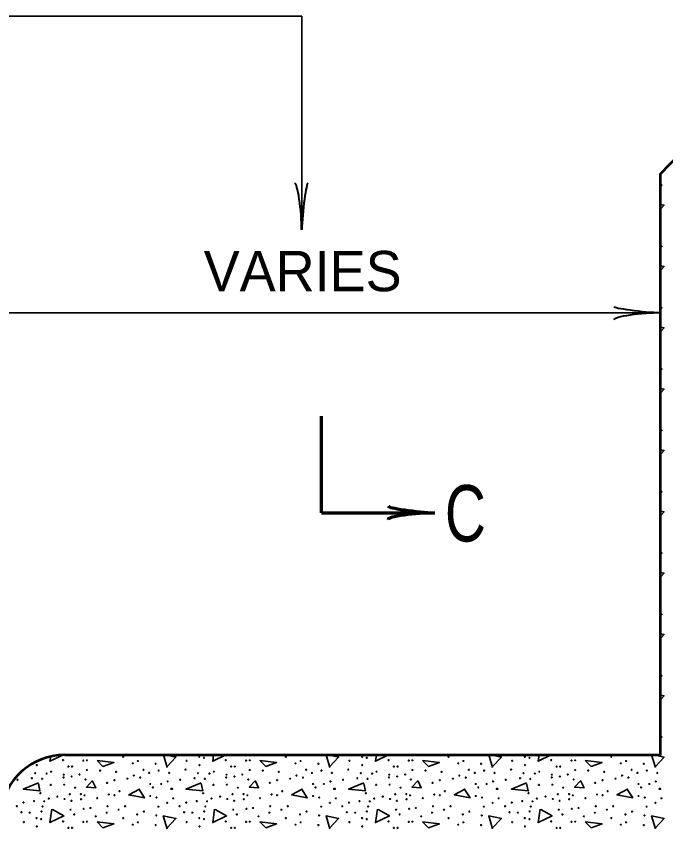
# Model space of a CAD drawing. Extents: x -105 to 751, y -65 to 479.
# Drawn here: x 57.8 to 106.1, y 28.3 to 88.7 of the extents above; entities that cross this region are included whole.
import ezdxf

# ---------------------------------------------------------------- set-up
doc = ezdxf.new("R2010")
doc.units = 0
doc.header["$LTSCALE"] = 1.2
doc.layers.add('1', color=7, linetype='Continuous', lineweight=35)

msp = doc.modelspace()

# ---------------------------------------------------------------- linework, layer by layer
at = {"layer": '1', "lineweight": 70}
for q in [(80.525, 58.96), (88.925, 51.76)]:
    msp.add_line((80.525, 51.76), q, dxfattribs=at)
at = {"layer": '1'}
for p, q in [((69.062, 32.832), (68.784, 33.76)), ((81.158, 32.832), (80.88, 33.76)), ((93.254, 32.832), (92.976, 33.76)), ((105.35, 32.832), (105.072, 33.76))]:
    msp.add_line(p, q, dxfattribs=at)
for points in [[(50.512, 88.687), (79.059, 88.687), (79.059, 72.823)], [(105.725, 74.696), (105.998, 74.64), (105.725, 74.347)], [(105.725, 70.136), (105.998, 70.08), (105.725, 69.787)], [(-1.897, 66.639), (54.365, 66.639), (105.725, 66.639)], [(105.725, 65.576), (105.998, 65.52), (105.725, 65.227)], [(105.725, 61.016), (105.998, 60.96), (105.725, 60.667)], [(105.725, 56.456), (105.998, 56.4), (105.725, 56.107)], [(105.725, 51.896), (105.998, 51.84), (105.725, 51.547)], [(105.725, 47.336), (105.998, 47.28), (105.725, 46.987)], [(105.725, 42.776), (105.998, 42.72), (105.725, 42.427)], [(105.725, 38.216), (105.998, 38.16), (105.725, 37.867)], [(61.299, 33.751), (60.35, 33.288), (60.387, 33.549)], [(68.929, 33.76), (69.71, 33.6), (69.038, 32.88)], [(73.413, 33.76), (72.446, 33.288), (72.513, 33.76)], [(81.025, 33.76), (81.806, 33.6), (81.134, 32.88)], [(85.509, 33.76), (84.542, 33.288), (84.609, 33.76)], [(93.121, 33.76), (93.902, 33.6), (93.23, 32.88)], [(97.605, 33.76), (96.638, 33.288), (96.705, 33.76)], [(105.217, 33.76), (105.998, 33.6), (105.326, 32.88)], [(59.486, 31.68), (58.358, 31.224), (59.606, 31.08), (59.486, 31.632)], [(63.518, 31.848), (63.062, 31.368), (63.758, 31.32), (63.518, 31.8)], [(71.582, 31.68), (70.454, 31.224), (71.702, 31.08), (71.582, 31.632)], [(75.614, 31.848), (75.158, 31.368), (75.854, 31.32), (75.614, 31.8)], [(83.678, 31.68), (82.55, 31.224), (83.798, 31.08), (83.678, 31.632)], [(87.71, 31.848), (87.254, 31.368), (87.95, 31.32), (87.71, 31.8)], [(95.774, 31.68), (94.646, 31.224), (95.894, 31.08), (95.774, 31.632)], [(99.806, 31.848), (99.35, 31.368), (100.046, 31.32), (99.806, 31.8)], [(66.998, 31.224), (66.206, 30.792), (67.382, 30.576), (66.95, 31.248)], [(79.094, 31.224), (78.302, 30.792), (79.478, 30.576), (79.046, 31.248)], [(91.19, 31.224), (90.398, 30.792), (91.574, 30.576), (91.142, 31.248)], [(103.286, 31.224), (102.494, 30.792), (103.67, 30.576), (103.238, 31.248)], [(60.542, 29.712), (61.382, 29.232), (60.35, 28.728), (60.494, 29.736)], [(72.638, 29.712), (73.478, 29.232), (72.446, 28.728), (72.59, 29.736)], [(84.734, 29.712), (85.574, 29.232), (84.542, 28.728), (84.686, 29.736)], [(96.83, 29.712), (97.67, 29.232), (96.638, 28.728), (96.782, 29.736)], [(69.062, 28.272), (68.774, 29.232), (69.71, 29.04), (69.038, 28.32)], [(81.158, 28.272), (80.87, 29.232), (81.806, 29.04), (81.134, 28.32)], [(93.254, 28.272), (92.966, 29.232), (93.902, 29.04), (93.23, 28.32)], [(105.35, 28.272), (105.062, 29.232), (105.998, 29.04), (105.326, 28.32)]]:
    msp.add_lwpolyline(points, dxfattribs=at)
at = {"layer": '1', "lineweight": 53}
msp.add_lwpolyline([(61.447, 33.76), (105.725, 33.76), (105.725, 76.96), (109.893, 81.276)], dxfattribs=at)
at = {"layer": '1'}
for points in [[(63.854, 33.336), (65.102, 33.192), (64.286, 32.904)], [(75.95, 33.336), (77.198, 33.192), (76.382, 32.904)], [(88.046, 33.336), (89.294, 33.192), (88.478, 32.904)], [(100.142, 33.336), (101.39, 33.192), (100.574, 32.904)], [(63.854, 28.776), (65.102, 28.632), (64.286, 28.344)], [(75.95, 28.776), (77.198, 28.632), (76.382, 28.344)], [(88.046, 28.776), (89.294, 28.632), (88.478, 28.344)], [(100.142, 28.776), (101.39, 28.632), (100.574, 28.344)]]:
    msp.add_lwpolyline(points, close=True, dxfattribs=at)
for centre in [(105.797, 76.132), (105.797, 71.572), (105.797, 67.012), (105.797, 62.452), (105.797, 57.892), (105.797, 53.332), (105.797, 48.772), (105.797, 44.212), (105.797, 39.652), (105.797, 35.092), (61.325, 33.374), (62.829, 33.34), (63.1, 33.358), (65.788, 33.629), (66.885, 33.311), (70.511, 33.326), (71.449, 33.629), (71.799, 33.549), (73.421, 33.374), (74.925, 33.34), (75.196, 33.358), (77.884, 33.629), (78.981, 33.311), (82.607, 33.326), (83.545, 33.629), (83.895, 33.549), (85.517, 33.374), (87.021, 33.34), (87.292, 33.358), (89.98, 33.629), (91.077, 33.311), (94.703, 33.326), (95.641, 33.629), (95.991, 33.549), (97.613, 33.374), (99.117, 33.34), (99.388, 33.358), (102.076, 33.629), (103.173, 33.311), (59.369, 33.008), (61.723, 32.897), (61.993, 32.897), (63.1, 32.642), (64.07, 32.595), (66.503, 33.136), (67.299, 32.658), (68.205, 33.104), (68.428, 32.595), (70.432, 32.674), (71.465, 33.008), (73.819, 32.897), (74.089, 32.897), (75.196, 32.642), (76.166, 32.595), (78.599, 33.136), (79.395, 32.658), (80.301, 33.104), (80.524, 32.595), (82.528, 32.674), (83.561, 33.008), (85.915, 32.897), (86.185, 32.897), (87.292, 32.642), (88.262, 32.595), (90.695, 33.136), (91.491, 32.658), (92.397, 33.104), (92.62, 32.595), (94.624, 32.674), (95.657, 33.008), (98.011, 32.897), (98.281, 32.897), (99.388, 32.642), (100.358, 32.595), (102.791, 33.136), (103.587, 32.658), (104.493, 33.104), (104.716, 32.595), (59.004, 32.028), (59.258, 32.404), (60.101, 32.372), (60.435, 32.515), (61.357, 32.091), (61.373, 32.292), (61.962, 32.155), (62.55, 32.308), (65.263, 32.499), (66.106, 31.996), (66.583, 32.229), (67.06, 32.075), (67.728, 32.42), (69.207, 32.42), (71.1, 32.028), (71.354, 32.404), (72.197, 32.372), (72.531, 32.515), (73.453, 32.091), (73.469, 32.292), (74.058, 32.155), (74.646, 32.308), (77.359, 32.499), (78.202, 31.996), (78.679, 32.229), (79.156, 32.075), (79.824, 32.42), (81.303, 32.42), (83.196, 32.028), (83.45, 32.404), (84.293, 32.372), (84.627, 32.515), (85.549, 32.091), (85.565, 32.292), (86.154, 32.155), (86.742, 32.308), (89.455, 32.499), (90.298, 31.996), (90.775, 32.229), (91.252, 32.075), (91.92, 32.42), (93.399, 32.42), (95.292, 32.028), (95.546, 32.404), (96.389, 32.372), (96.723, 32.515), (97.645, 32.091), (97.661, 32.292), (98.25, 32.155), (98.838, 32.308), (101.551, 32.499), (102.394, 31.996), (102.871, 32.229), (103.348, 32.075), (104.016, 32.42), (105.495, 32.42), (57.938, 31.916), (59.767, 31.98), (60.403, 31.535), (61.405, 31.55), (62.989, 31.932), (64.595, 31.678), (65.136, 31.884), (67.807, 31.598), (68.619, 31.598), (69.096, 31.789), (70.034, 31.916), (71.863, 31.98), (72.499, 31.535), (73.501, 31.55), (75.085, 31.932), (76.691, 31.678), (77.232, 31.884), (79.903, 31.598), (80.715, 31.598), (81.192, 31.789), (82.13, 31.916), (83.959, 31.98), (84.595, 31.535), (85.597, 31.55), (87.181, 31.932), (88.787, 31.678), (89.328, 31.884), (91.999, 31.598), (92.811, 31.598), (93.288, 31.789), (94.226, 31.916), (96.055, 31.98), (96.691, 31.535), (97.693, 31.55), (99.277, 31.932), (100.883, 31.678), (101.424, 31.884), (104.095, 31.598), (104.907, 31.598), (105.384, 31.789), (59.64, 30.914), (61.818, 30.835), (62.216, 31.328), (62.646, 30.85), (64.722, 30.819), (65.517, 31.057), (67.998, 31.344), (69.366, 31.232), (69.43, 31.232), (71.736, 30.914), (73.914, 30.835), (74.312, 31.328), (74.742, 30.85), (76.818, 30.819), (77.613, 31.057), (80.094, 31.344), (81.462, 31.232), (81.526, 31.232), (83.832, 30.914), (86.01, 30.835), (86.408, 31.328), (86.838, 30.85), (88.914, 30.819), (89.709, 31.057), (92.19, 31.344), (93.558, 31.232), (93.622, 31.232), (95.928, 30.914), (98.106, 30.835), (98.504, 31.328), (98.934, 30.85), (101.01, 30.819), (101.805, 31.057), (104.286, 31.344), (105.654, 31.232), (105.718, 31.232), (58.383, 30.214), (59.163, 30.326), (59.926, 30.31), (60.26, 30.516), (60.896, 30.66), (61.437, 30.485), (61.946, 30.357), (62.661, 30.469), (62.925, 30.755), (63.863, 30.548), (65.136, 30.771), (67.807, 30.707), (68.269, 30.596), (69.064, 30.198), (69.509, 30.532), (70.479, 30.214), (71.259, 30.326), (72.022, 30.31), (72.356, 30.516), (72.992, 30.66), (73.533, 30.485), (74.042, 30.357), (74.757, 30.469), (75.021, 30.755), (75.959, 30.548), (77.232, 30.771), (79.903, 30.707), (80.365, 30.596), (81.16, 30.198), (81.605, 30.532), (82.575, 30.214), (83.355, 30.326), (84.118, 30.31), (84.452, 30.516), (85.088, 30.66), (85.629, 30.485), (86.138, 30.357), (86.853, 30.469), (87.117, 30.755), (88.055, 30.548), (89.328, 30.771), (91.999, 30.707), (92.461, 30.596), (93.256, 30.198), (93.701, 30.532), (94.671, 30.214), (95.451, 30.326), (96.214, 30.31), (96.548, 30.516), (97.184, 30.66), (97.725, 30.485), (98.234, 30.357), (98.949, 30.469), (99.213, 30.755), (100.151, 30.548), (101.424, 30.771), (104.095, 30.707), (104.557, 30.596), (105.352, 30.198), (105.797, 30.532), (57.89, 29.944), (59.799, 29.928), (61.882, 29.689), (62.852, 29.753), (63.354, 29.816), (64.627, 29.944), (65.454, 29.689), (65.931, 29.944), (68.412, 29.912), (69.986, 29.944), (71.895, 29.928), (73.978, 29.689), (74.948, 29.753), (75.45, 29.816), (76.723, 29.944), (77.55, 29.689), (78.027, 29.944), (80.508, 29.912), (82.082, 29.944), (83.991, 29.928), (86.074, 29.689), (87.044, 29.753), (87.546, 29.816), (88.819, 29.944), (89.646, 29.689), (90.123, 29.944), (92.604, 29.912), (94.178, 29.944), (96.087, 29.928), (98.17, 29.689), (99.14, 29.753), (99.642, 29.816), (100.915, 29.944), (101.742, 29.689), (102.219, 29.944), (104.7, 29.912), (58.224, 29.498), (58.844, 29.466), (59.353, 29.069), (59.703, 28.989), (59.719, 29.562), (62.152, 29.339), (63.752, 29.196), (64.563, 29.466), (65.788, 29.069), (66.837, 29.339), (67.33, 29.546), (68.253, 29.26), (70.32, 29.498), (70.94, 29.466), (71.449, 29.069), (71.799, 28.989), (71.815, 29.562), (74.248, 29.339), (75.848, 29.196), (76.659, 29.466), (77.884, 29.069), (78.933, 29.339), (79.426, 29.546), (80.349, 29.26), (82.416, 29.498), (83.036, 29.466), (83.545, 29.069), (83.895, 28.989), (83.911, 29.562), (86.344, 29.339), (87.944, 29.196), (88.755, 29.466), (89.98, 29.069), (91.029, 29.339), (91.522, 29.546), (92.445, 29.26), (94.512, 29.498), (95.132, 29.466), (95.641, 29.069), (95.991, 28.989), (96.007, 29.562), (98.44, 29.339), (100.04, 29.196), (100.851, 29.466), (102.076, 29.069), (103.125, 29.339), (103.618, 29.546), (104.541, 29.26), (58.415, 28.766), (59.369, 28.448), (61.325, 28.814), (62.829, 28.78), (63.1, 28.798), (66.503, 28.576), (66.885, 28.751), (68.205, 28.544), (70.511, 28.766), (71.465, 28.448), (73.421, 28.814), (74.925, 28.78), (75.196, 28.798), (78.599, 28.576), (78.981, 28.751), (80.301, 28.544), (82.607, 28.766), (83.561, 28.448), (85.517, 28.814), (87.021, 28.78), (87.292, 28.798), (90.695, 28.576), (91.077, 28.751), (92.397, 28.544), (94.703, 28.766), (95.657, 28.448), (97.613, 28.814), (99.117, 28.78), (99.388, 28.798), (102.791, 28.576), (103.173, 28.751), (104.493, 28.544), (61.723, 28.337), (61.993, 28.337), (73.819, 28.337), (74.089, 28.337), (85.915, 28.337), (86.185, 28.337), (98.011, 28.337), (98.281, 28.337)]:
    msp.add_circle(centre, 0.0318, dxfattribs=at)
for centre, start, end in [((105.718, 76.832), 283.20427, 76.79573), ((105.718, 72.272), 283.20427, 76.79573), ((105.718, 67.712), 283.20427, 76.79573), ((105.718, 63.152), 283.20427, 76.79573), ((105.718, 58.592), 283.20427, 76.79573), ((105.718, 54.032), 283.20427, 76.79573), ((105.718, 49.472), 283.20427, 76.79573), ((105.718, 44.912), 283.20427, 76.79573), ((105.718, 40.352), 283.20427, 76.79573), ((105.718, 35.792), 283.20427, 76.79573), ((63.752, 33.756), 173.03471, 6.96529), ((75.848, 33.756), 173.03471, 6.96529), ((87.944, 33.756), 173.03471, 6.96529), ((100.04, 33.756), 173.03471, 6.96529)]:
    msp.add_arc(centre, 0.0318, start, end, dxfattribs=at)
at = {"layer": '1', "lineweight": 53}
msp.add_arc((61.447, 28.96), 4.8, 90, 173.99999, dxfattribs=at)
at = {"layer": '1', "lineweight": 40}
for centre, major_axis, ratio, start_param, end_param in [((78.727, 74.132), (0.187, -2.143), 0.122415, 0.896353, 3.141593), ((79.313, 74.167), (-0.211, -2.108), 0.07063, 3.140715, 5.41811), ((104.38, 66.893), (2.108, -0.211), 0.07063, 3.140715, 5.41811), ((104.415, 66.307), (2.143, 0.187), 0.122415, 0.896353, 3.141593)]:
    msp.add_ellipse(centre, major_axis=major_axis, ratio=ratio, start_param=start_param, end_param=end_param, dxfattribs=at)
at = {"layer": '1', "lineweight": 70}
for centre, major_axis, ratio, start_param, end_param in [((87.594, 52.018), (2.105, -0.233), 0.07063, 3.140715, 5.41811), ((87.623, 51.432), (2.145, 0.165), 0.122415, 0.896353, 3.141593)]:
    msp.add_ellipse(centre, major_axis=major_axis, ratio=ratio, start_param=start_param, end_param=end_param, dxfattribs=at)

# ---------------------------------------------------------------- texts
at = {"layer": '1'}
msp.add_text('VARIES', height=3, dxfattribs=at).set_placement((71.775, 68.24))
at = {"layer": '1', "width": 0.75}
msp.add_text('C', height=4.2, dxfattribs=at).set_placement((89.706, 49.629))

doc.saveas('drawing.dxf')
